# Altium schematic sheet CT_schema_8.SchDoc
size 371 x 245 mm
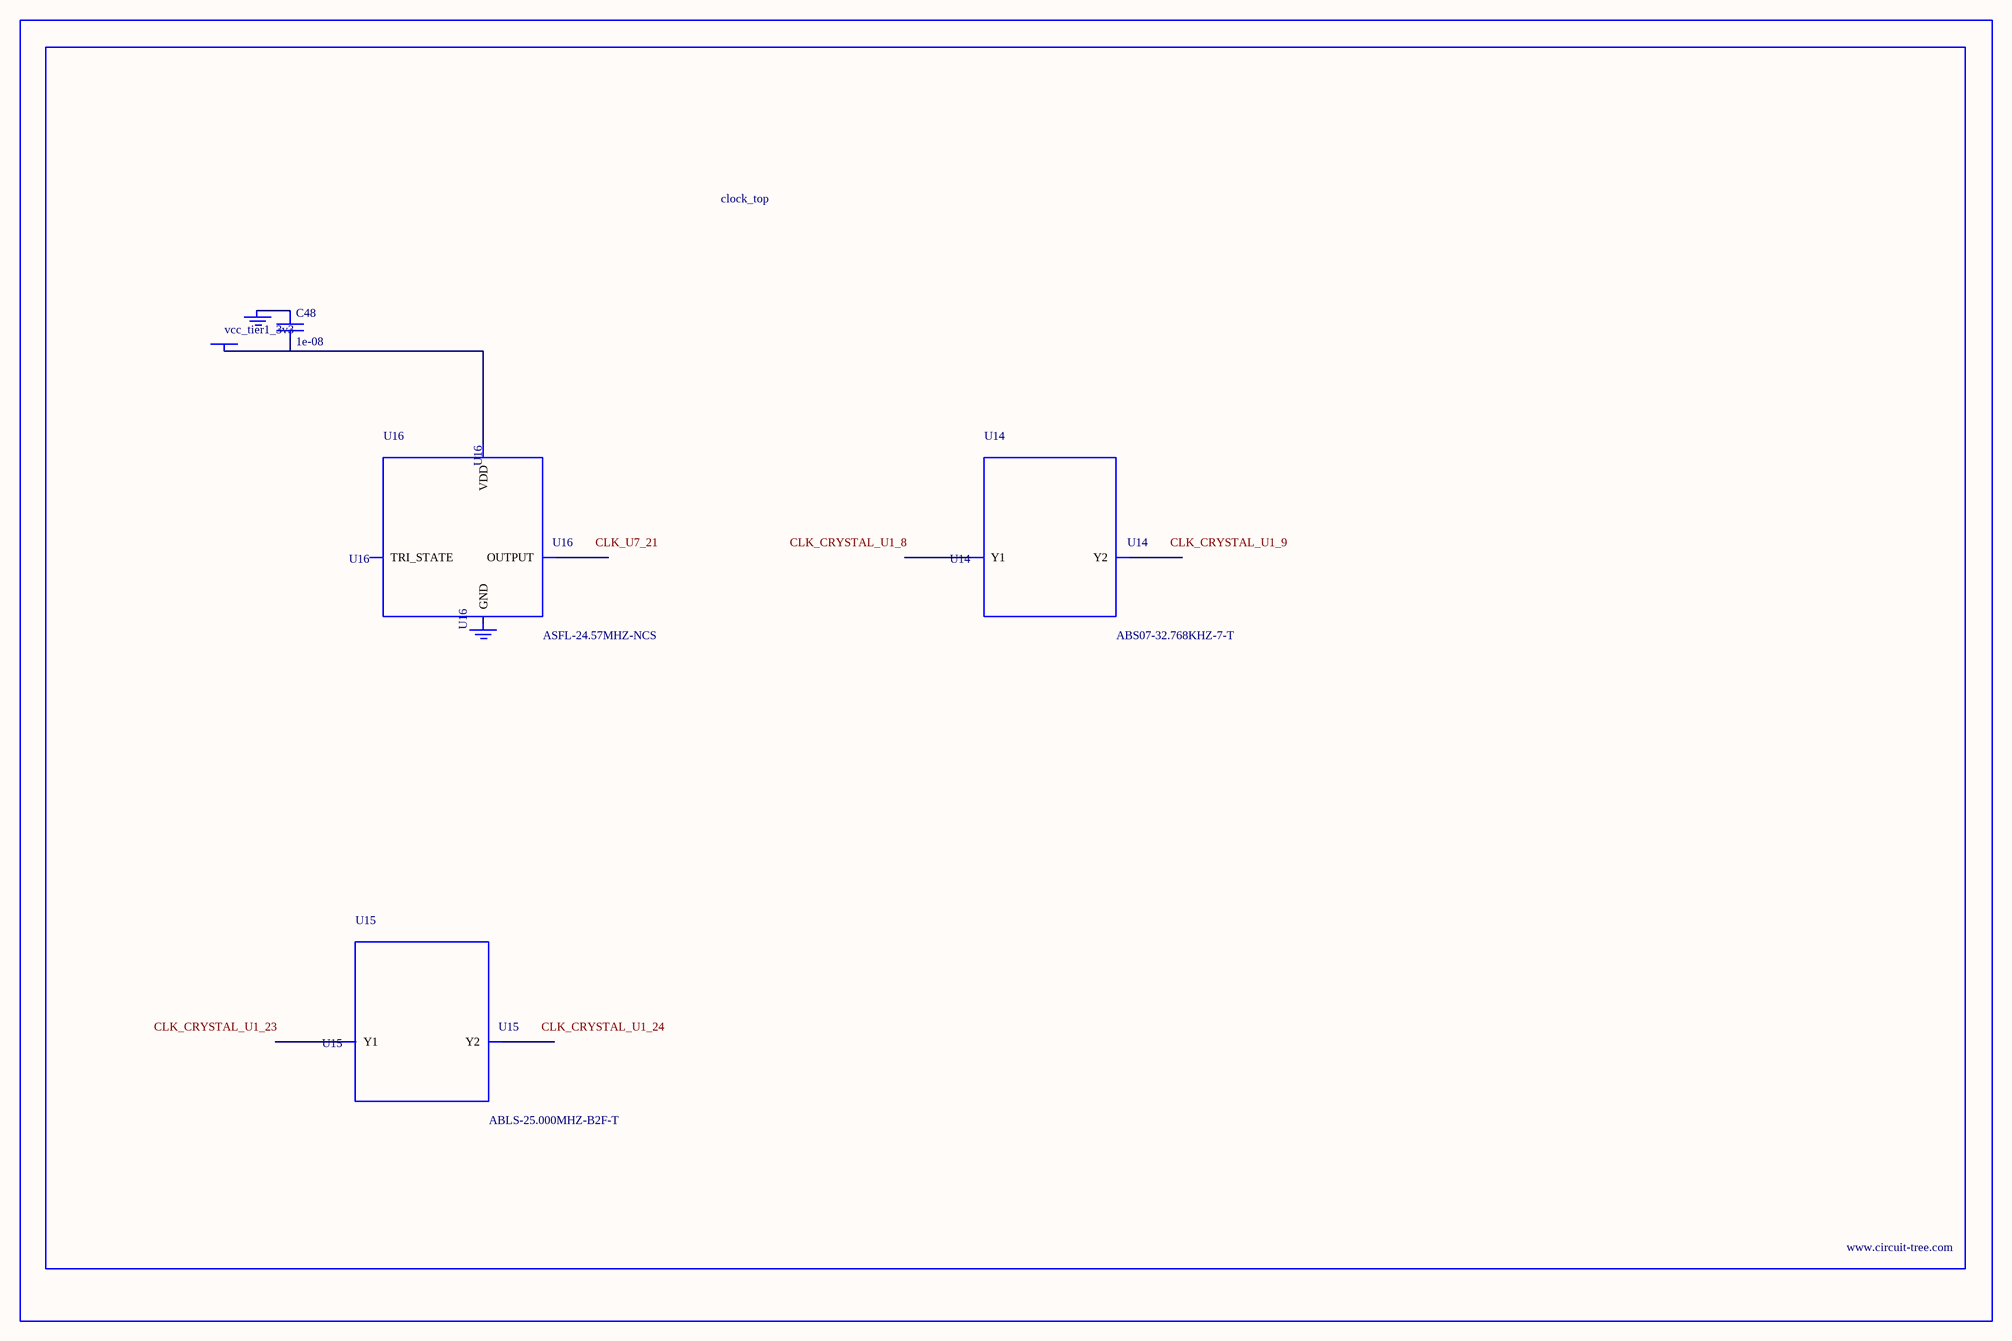
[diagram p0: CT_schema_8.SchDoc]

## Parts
BORDER7  (no value)
C48  1e-08  [C0402]
GND_INSTANCE_7_0  (no value)
GND_INSTANCE_7_1  (no value)
POWER_INSTANCE_7_0  vcc_tier1_3v3
U14  ABS07-32.768KHZ-7-T  [ABS07-32.768KHZ-7-T]
U15  ABLS-25.000MHZ-B2F-T  [ABLS-25.000MHZ-B2F-T]
U16  ASFL-24.57MHZ-NCS  [ASFL1]

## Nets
NetC48_1: C48.1 GND_INSTANCE_7_0.0(GND)
NetC48_2: C48.2 POWER_INSTANCE_7_0.0(PWR) U16.4(VDD)

Not connected (* = marked no-connect by the designer): GND_INSTANCE_7_1 0(GND); U14 1(Y1) 2(Y2); U15 1(Y1) 2(Y2); U16 1(TRI_STATE) 2(GND) 3(OUTPUT)

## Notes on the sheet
- Labels drawn without touching a wire or pin: CLK_CRYSTAL_U1_8, CLK_CRYSTAL_U1_9, CLK_CRYSTAL_U1_23, CLK_CRYSTAL_U1_24, CLK_U7_21

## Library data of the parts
BORDER7 = BORDER_PAGE7
C48 = C0402C103K3RAC
GND_INSTANCE_7_0 GND_INSTANCE_7_1 = GND
POWER_INSTANCE_7_0 = PWR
